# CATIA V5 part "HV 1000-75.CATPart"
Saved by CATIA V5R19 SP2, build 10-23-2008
Part number: HV 1000-75
Bounding box of the stored display mesh (mm): x -24.865 to 24.865, y -24.997 to 24.997, z 0 to 207
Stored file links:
  C:\Users\Bora\Desktop\3D KATI MODEL- CATIA PART\HV serisi\HV 1000\HV 1000-75.CATPart
  C:\Program Files\Dassault Systemes\B19\intel_a\reffiles\standard\MetricThickPitch.txt
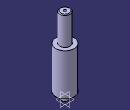
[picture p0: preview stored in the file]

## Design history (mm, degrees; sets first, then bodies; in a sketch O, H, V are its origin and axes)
Body1 (main body)
  Sketch1 on yz-plane, origin (0, 0, 0), H (0, 1, 0), V (0, 0, 1)
    point P1 (14, 205)
    point P3 (14, 205)
    point P8 (8, 17)
    point P10 (8, 1)
    point P11 (8, 17)
    point P12 (8, 1)
    arc A1 centre (12, 205) radius 2 from (14, 205) to (12, 207) ccw
    line L1 (14, 205) -> (14, 131)
    arc A2 centre (8, 18) radius 1 from (8, 19) to (8, 17) ccw
    line L2 (7, 0) -> (8, 1)
    line L3 (8, 17) -> (8, 1)
    line L4 (0, 0) -> (7, 0)
    line L5 (8, 19) -> (25, 19)
    line L6 (14, 131) -> (25, 131)
    line L7 (12, 207) -> (0, 207)
    line L8 (25, 131) -> (25, 19)
    horizontal: L4 H, L5 H, L6 H
    tangency: L7 A1
    vertical: L8 V
    coincidence: P1 P3, P8 P11, P10 P12
  Shaft1: profile Sketch1, axis Sketch1.V, angle 360
  Sketch2 on face of Shaft1 from Sketch1.L4, origin (0, 0, 0), H (1, 0, 0), V (0, -1, 0)
    point P1 (0, 0)
  Hole1: placed by Sketch2, at (0, 0, 0) direction (0, 0, 1), diameter 13.835, depth 19, threaded "M16", thread diameter 16, thread depth 19, pitch 2
  Sketch3 on face of Shaft1 from Sketch1.L7, origin (0, 0, 207), H (1, 0, 0), V (0, 1, 0)
    point P1 (0, 0)
  Hole2: placed by Sketch3, at (0, 0, 207) direction (0, 0, -1), diameter 6.647, depth 15, threaded "M8", thread diameter 8, thread depth 15, pitch 1.25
